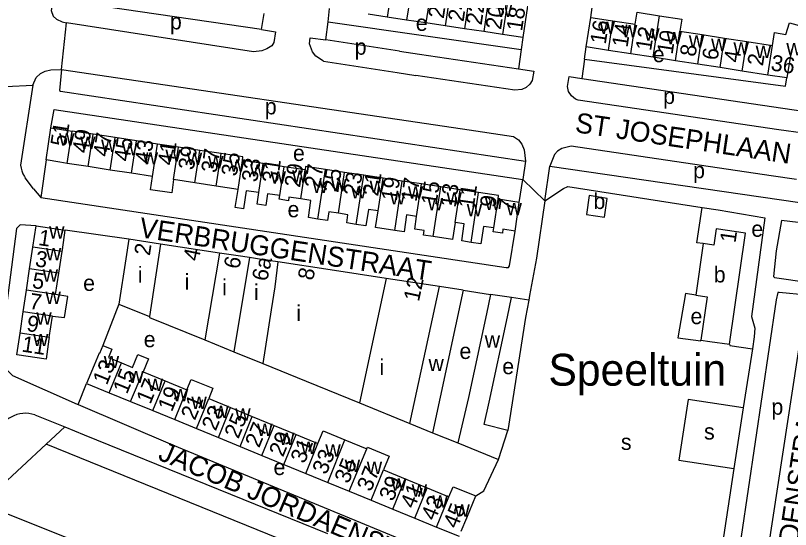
# Model space of a CAD drawing. Extents: x 163012 to 165277, y 382513 to 383987.
# Drawn here: x 163538.9 to 163733.4, y 383095.1 to 383224 of the extents above; entities that cross this region are included whole.
import ezdxf

# ---------------------------------------------------------------- set-up
doc = ezdxf.new("R2010")
doc.units = 0
for name, color, linetype in [('BLT_Basislijn', 7, 'Continuous'), ('BLT_Bebouwing', 7, 'Continuous'), ('BLT_Centroide', 7, 'Continuous'), ('BLT_Huisnummer', 7, 'Continuous'), ('BLT_Huisnummer_ tussenligend', 7, 'Continuous'), ('BLT_Onderverdeling_panden', 7, 'Continuous'), ('BLT_Straatnaam', 7, 'Continuous'), ('BLT_Terrein_beschrifting', 7, 'Continuous'), ('BLT_Vlakafsluiter', 7, 'Continuous')]:
    doc.layers.add(name, color=color, linetype=linetype)

msp = doc.modelspace()

# ---------------------------------------------------------------- linework, layer by layer
at = {"layer": 'BLT_Basislijn'}
for p, q in [((163683.27, 383223.5), (163685.34, 383238.89)), ((163617.35, 383222.35), (163617.75, 383225.74)), ((163600.65, 383220.44), (163601.31, 383224.5)), ((163616.82, 383217.83), (163617.35, 383222.35)), ((163617.35, 383222.35), (163665.8, 383215.42)), ((163666.2, 383218.45), (163665.8, 383215.42)), ((163665.8, 383215.42), (163665.17, 383210.56)), ((163681.74, 383213.01), (163682.13, 383216.08)), ((163681.74, 383213.01), (163681.06, 383208.19)), ((163616.19, 383212.49), (163634.73, 383209.65)), ((163634.73, 383209.65), (163639.41, 383208.92)), ((163543.28, 383206.52), (163540.17, 383186.47)), ((163730.5, 383195.29), (163680.12, 383202.7)), ((163547.8, 383195.77), (163548.59, 383200.4)), ((163548.59, 383200.4), (163666.28, 383182.82)), ((163546.58, 383187.75), (163545.29, 383178.34)), ((163543.44, 383180.49), (163541.32, 383183.29)), ((163665.36, 383177.07), (163666.28, 383182.82)), ((163543.44, 383180.49), (163545.29, 383178.34)), ((163567.32, 383167.86), (163551.4, 383170.14)), ((163651.24, 383155.07), (163658.14, 383154.04)), ((163667.74, 383152.57), (163663.43, 383153.24)), ((163737.55, 383153.8), (163724.03, 383065.99)), ((163564.84, 383151.6), (163560.83, 383141.22)), ((163723.85, 383140.41), (163721.57, 383125.56)), ((163554.64, 383126.39), (163556.76, 383131.68)), ((163721.57, 383125.56), (163719.24, 383110.34)), ((163543.78, 383123.82), (163551.25, 383120.79)), ((163551.25, 383120.79), (163546.61, 383116.48)), ((163551.25, 383120.79), (163556.14, 383118.81)), ((163556.14, 383118.81), (163617.19, 383094.03)), ((163643.57, 383119.33), (163649.89, 383116.83)), ((163546.61, 383116.48), (163530.49, 383101.51)), ((163712.98, 383049.04), (163546.61, 383116.48)), ((163719.24, 383110.34), (163712.93, 383069.21))]:
    msp.add_line(p, q, dxfattribs=at)
for points in [[(163548.32, 383228.18), (163547.89, 383225.23), (163548.33, 383223.8), (163549.18, 383223.01), (163550.64, 383222.36), (163551.73, 383222.16)], [(163600.65, 383220.44), (163548.32, 383228.18)], [(163600.65, 383220.44), (163604.17, 383219.84), (163603.76, 383217.22), (163603.24, 383216.36), (163602, 383215.57), (163600.74, 383215.07), (163598.63, 383214.87), (163551.73, 383222.16)], [(163616.19, 383212.49), (163614.25, 383213.75), (163613.43, 383214.84), (163612.68, 383216.9), (163612.89, 383218.37), (163616.82, 383217.83)], [(163635.28, 383215.03), (163616.82, 383217.83)], [(163635.28, 383215.03), (163640.28, 383214.25), (163665.17, 383210.56)], [(163681.74, 383213.01), (163732.21, 383206.25), (163732.54, 383208.3)], [(163543.28, 383206.52), (163544.06, 383208.45), (163545.18, 383209.44), (163546.38, 383210.05), (163547.77, 383210.35), (163550.43, 383210.46)], [(163550.43, 383210.46), (163549.94, 383205.12), (163550.2, 383204.96), (163666.92, 383187.41)], [(163550.43, 383210.46), (163651.06, 383195.58), (163663.91, 383193.63), (163665.14, 383192.82), (163665.95, 383191.74), (163666.61, 383190.28), (163666.92, 383187.41)], [(163665.17, 383210.56), (163668.97, 383210), (163668.61, 383207.65), (163668, 383206.72), (163667.11, 383205.89), (163665.99, 383205.38), (163664.21, 383205.22), (163639.41, 383208.92)], [(163680.12, 383202.7), (163679.46, 383203), (163678.46, 383203.86), (163677.67, 383204.95), (163677.49, 383206.17), (163677.86, 383208.64), (163681.06, 383208.19)], [(163681.06, 383208.19), (163743.95, 383198.89)], [(163736.58, 383194.42), (163730.5, 383195.29)], [(163728.59, 383183.8), (163678.33, 383191.17), (163676.02, 383190.64), (163674.95, 383189.93), (163674.15, 383189.07), (163673.01, 383186.2)], [(163540.17, 383186.47), (163540.29, 383185.72), (163540.5, 383184.98), (163540.78, 383184.27), (163541.14, 383183.59), (163541.32, 383183.29)], [(163666.92, 383187.41), (163666.28, 383182.82)], [(163671.78, 383177.48), (163673.01, 383186.2)], [(163673.01, 383186.2), (163740.39, 383176.4)], [(163734.93, 383182.84), (163728.59, 383183.8)], [(163671.78, 383177.48), (163676.41, 383180.57), (163677.57, 383181.06), (163711.25, 383175.83)], [(163545.29, 383178.34), (163662.05, 383160.74), (163662.63, 383160.75), (163662.91, 383161.17), (163664.28, 383169.9)], [(163671.78, 383177.48), (163669.71, 383163.15), (163667.95, 383153.73), (163667.74, 383152.57)], [(163711.51, 383166.75), (163709.91, 383166.99), (163711.25, 383175.83)], [(163711.25, 383175.83), (163715.3, 383175.2), (163726.95, 383173.25), (163723.67, 383148.52), (163723.98, 383147.31), (163724.46, 383145.55), (163724.31, 383143.4), (163723.85, 383140.41)], [(163740.23, 383171.45), (163731.14, 383172.58), (163729.82, 383164.91), (163729.17, 383158.51), (163729.43, 383158.26), (163738.07, 383157.02)], [(163544.06, 383171.23), (163540.11, 383171.45), (163539.19, 383170.51), (163535.17, 383139.55), (163535.35, 383137.13), (163535.71, 383136.14), (163538.14, 383133.7), (163554.35, 383126.52), (163554.64, 383126.39)], [(163737.55, 383153.8), (163730.58, 383154.54), (163730.22, 383154.47), (163729.85, 383152.69), (163717.55, 383069.54), (163717.76, 383068.49), (163724.03, 383065.99)], [(163709.65, 383153.82), (163707.09, 383154.26), (163705.18, 383143.11), (163710.9, 383142.39), (163710.93, 383142.57)], [(163667.74, 383152.57), (163666.93, 383148.19), (163662.45, 383119.93)], [(163718.09, 383141.54), (163718.17, 383141.25), (163723.85, 383140.41)], [(163721.57, 383125.56), (163707.76, 383127.68), (163705.39, 383112.46), (163719.24, 383110.34)], [(163554.64, 383126.39), (163578.32, 383116.28), (163648.13, 383087.42)], [(163543.78, 383123.82), (163543.03, 383124.03), (163542.27, 383124.16), (163541.49, 383124.2), (163540.72, 383124.17), (163539.96, 383124.06), (163539.21, 383123.87), (163538.48, 383123.61), (163537.78, 383123.27), (163537.12, 383122.86), (163536.51, 383122.39), (163536.02, 383121.92)], [(163654.41, 383103.48), (163656.43, 383104.8), (163660.11, 383112.66)], [(163530.49, 383101.51), (163628.79, 383062.23), (163673.84, 383043.82), (163676.87, 383042.07), (163681.18, 383038.49), (163684.68, 383034.25), (163686.91, 383030.27), (163688.82, 383025.72), (163689.82, 383019.32), (163689.3, 383011.06), (163686.97, 383004.69), (163680.5, 382995.96)]]:
    msp.add_lwpolyline(points, dxfattribs=at)
at = {"layer": 'BLT_Bebouwing'}
for p, q in [((163667.38, 383226.28), (163666.2, 383218.45)), ((163632.21, 383223.56), (163627.42, 383224.28)), ((163637.08, 383222.83), (163632.21, 383223.56)), ((163641.92, 383222.1), (163637.08, 383222.83)), ((163682.13, 383216.08), (163683.27, 383223.5)), ((163688.87, 383222.63), (163694.47, 383221.77)), ((163646.72, 383221.38), (163641.92, 383222.1)), ((163651.57, 383220.65), (163646.72, 383221.38)), ((163733.19, 383222.15), (163736.56, 383221.23)), ((163656.42, 383219.92), (163651.57, 383220.65)), ((163661.15, 383219.21), (163656.42, 383219.92)), ((163666.2, 383218.45), (163661.15, 383219.21)), ((163705.68, 383220.04), (163711.28, 383219.18)), ((163711.28, 383219.18), (163716.88, 383218.31)), ((163728.88, 383216.46), (163729.42, 383219.71)), ((163716.88, 383218.31), (163722.48, 383217.45)), ((163722.48, 383217.45), (163728.88, 383216.46)), ((163687.73, 383215.21), (163682.13, 383216.08)), ((163693.33, 383214.35), (163687.73, 383215.21)), ((163733.64, 383215.44), (163732.54, 383208.3)), ((163698.93, 383213.49), (163693.33, 383214.35)), ((163704.53, 383212.62), (163698.93, 383213.49)), ((163710.13, 383211.76), (163704.53, 383212.62)), ((163715.73, 383210.89), (163710.13, 383211.76)), ((163721.33, 383210.03), (163715.73, 383210.89)), ((163727.74, 383209.04), (163721.33, 383210.03)), ((163732.54, 383208.3), (163727.74, 383209.04)), ((163546.58, 383187.75), (163547.8, 383195.77)), ((163547.8, 383195.77), (163553.11, 383194.97)), ((163558.39, 383194.17), (163553.11, 383194.97)), ((163563.92, 383193.34), (163558.39, 383194.17)), ((163569.23, 383192.54), (163563.92, 383193.34)), ((163574.55, 383191.74), (163569.23, 383192.54)), ((163579.82, 383190.94), (163574.55, 383191.74)), ((163585.17, 383190.14), (163579.82, 383190.94)), ((163590.53, 383189.33), (163585.17, 383190.14)), ((163601.1, 383186.83), (163595.85, 383187.62)), ((163557.12, 383186.07), (163551.85, 383186.88)), ((163562.69, 383185.22), (163557.12, 383186.07)), ((163606.34, 383186.04), (163601.1, 383186.83)), ((163611.58, 383185.25), (163606.34, 383186.04)), ((163568.01, 383184.41), (163562.69, 383185.22)), ((163573.32, 383183.6), (163568.01, 383184.41)), ((163621.49, 383184.63), (163616.68, 383185.36)), ((163626.3, 383183.9), (163621.49, 383184.63)), ((163631.15, 383183.17), (163626.3, 383183.9)), ((163583.95, 383182), (163578.59, 383182.81)), ((163589.3, 383181.19), (163583.95, 383182)), ((163635.99, 383182.44), (163631.15, 383183.17)), ((163640.82, 383181.72), (163635.99, 383182.44)), ((163594.76, 383180.37), (163589.3, 383181.19)), ((163645.64, 383180.99), (163640.82, 383181.72)), ((163650.48, 383180.26), (163645.64, 383180.99)), ((163655.13, 383179.56), (163650.48, 383180.26)), ((163665.36, 383177.07), (163660.01, 383177.88)), ((163664.28, 383169.9), (163665.36, 383177.07)), ((163543.26, 383165.85), (163544.06, 383171.23)), ((163544.06, 383171.23), (163551.4, 383170.14)), ((163575.33, 383166.64), (163567.32, 383167.86)), ((163590.12, 383164.38), (163575.33, 383166.64)), ((163711.51, 383166.75), (163709.65, 383153.82)), ((163714.17, 383166.37), (163711.51, 383166.75)), ((163542.45, 383160.46), (163543.26, 383165.85)), ((163549.79, 383159.37), (163550.59, 383164.76)), ((163594.82, 383163.67), (163590.12, 383164.38)), ((163597.62, 383163.24), (163594.82, 383163.67)), ((163601.62, 383162.63), (163597.62, 383163.24)), ((163604.71, 383162.16), (163601.62, 383162.63)), ((163541.65, 383155.08), (163542.45, 383160.46)), ((163617.84, 383160.16), (163604.71, 383162.16)), ((163548.98, 383153.98), (163549.79, 383159.37)), ((163631.97, 383158.01), (163617.84, 383160.16)), ((163645.33, 383155.97), (163631.97, 383158.01)), ((163540.84, 383149.69), (163541.65, 383155.08)), ((163651.24, 383155.07), (163643.57, 383119.33)), ((163651.24, 383155.07), (163645.33, 383155.97)), ((163663.43, 383153.24), (163658.14, 383154.04)), ((163564.84, 383151.6), (163572.56, 383148.48)), ((163540.04, 383144.3), (163540.84, 383149.69)), ((163547.37, 383143.2), (163548.18, 383148.59)), ((163586.43, 383142.61), (163593.66, 383139.66)), ((163710.93, 383142.57), (163713.14, 383142.25)), ((163713.14, 383142.25), (163718.09, 383141.54)), ((163593.66, 383139.66), (163600.97, 383136.68)), ((163600.97, 383136.68), (163611.86, 383132.25)), ((163570.97, 383134.61), (163576.45, 383132.37)), ((163556.76, 383131.68), (163562.42, 383129.36)), ((163576.45, 383132.37), (163581.93, 383130.12)), ((163611.86, 383132.25), (163625.26, 383126.83)), ((163562.42, 383129.36), (163567.76, 383127.18)), ((163587.41, 383127.89), (163592.89, 383125.65)), ((163567.76, 383127.18), (163573.38, 383124.87)), ((163625.26, 383126.83), (163637.88, 383121.64)), ((163573.38, 383124.87), (163578.86, 383122.62)), ((163598.33, 383123.4), (163603.83, 383121.15)), ((163578.86, 383122.62), (163584.33, 383120.38)), ((163637.88, 383121.64), (163643.57, 383119.33)), ((163584.33, 383120.38), (163589.81, 383118.13)), ((163603.83, 383121.15), (163609.33, 383118.9)), ((163589.81, 383118.13), (163595.26, 383115.9)), ((163609.33, 383118.9), (163614.81, 383116.65)), ((163595.26, 383115.9), (163600.76, 383113.65)), ((163621.57, 383117.56), (163627.11, 383115.31)), ((163600.76, 383113.65), (163606.26, 383111.39)), ((163606.26, 383111.39), (163611.76, 383109.14)), ((163631.26, 383109.99), (163636.73, 383107.74)), ((163611.76, 383109.14), (163617.26, 383106.88)), ((163617.26, 383106.88), (163622.68, 383104.66)), ((163636.73, 383107.74), (163642.21, 383105.49)), ((163622.68, 383104.66), (163628.15, 383102.42)), ((163642.21, 383105.49), (163647.69, 383103.25)), ((163628.15, 383102.42), (163633.63, 383100.17)), ((163633.63, 383100.17), (163639.11, 383097.93)), ((163639.11, 383097.93), (163644.59, 383095.68)), ((163644.59, 383095.68), (163650.26, 383093.36))]:
    msp.add_line(p, q, dxfattribs=at)
for points in [[(163694.47, 383221.77), (163694.94, 383224.78), (163700.54, 383223.91)], [(163683.27, 383223.5), (163688.21, 383222.73), (163688.87, 383222.63)], [(163700.54, 383223.91), (163706.14, 383223.05), (163705.68, 383220.04)], [(163729.42, 383219.71), (163732.23, 383219.23), (163733.19, 383222.15)], [(163551.85, 383186.88), (163550.05, 383187.16), (163546.58, 383187.75)], [(163595.85, 383187.62), (163595.98, 383188.51), (163590.53, 383189.33)], [(163616.68, 383185.36), (163611.71, 383186.1), (163611.58, 383185.25)], [(163578.59, 383182.81), (163578.14, 383179.47), (163572.82, 383180.27), (163573.32, 383183.6)], [(163600, 383179.54), (163596.78, 383180.02), (163596.1, 383175.49), (163594.07, 383175.8), (163594.76, 383180.37)], [(163605.25, 383178.79), (163602.15, 383179.26), (163601.71, 383176.32), (163599.56, 383176.64), (163600, 383179.54)], [(163610.49, 383178), (163607.52, 383178.45), (163607.39, 383177.53), (163605.11, 383177.87), (163605.25, 383178.79)], [(163614.8, 383172.91), (163612.4, 383173.27), (163613.05, 383177.61), (163610.49, 383178)], [(163660.01, 383177.88), (163660.15, 383178.8), (163655.13, 383179.56)], [(163619.94, 383174.38), (163617.54, 383174.74), (163617.21, 383172.55), (163614.8, 383172.91)], [(163624.44, 383171.57), (163622.03, 383171.94), (163622.34, 383174.01), (163619.94, 383174.38)], [(163629.92, 383174.98), (163627.48, 383175.35), (163626.86, 383171.21), (163624.44, 383171.57)], [(163634.13, 383170.08), (163629.29, 383170.81), (163629.92, 383174.98)], [(163639.59, 383173.57), (163637.08, 383173.95), (163636.44, 383169.73), (163634.13, 383170.08)], [(163643.76, 383168.55), (163641.33, 383168.92), (163641.5, 383170.01), (163639.11, 383170.37), (163639.59, 383173.57)], [(163550.59, 383164.76), (163550.66, 383165.19), (163551.4, 383170.14)], [(163649.25, 383172.03), (163648.61, 383167.82), (163643.76, 383168.55)], [(163653.31, 383167.08), (163650.9, 383167.43), (163651.54, 383171.69), (163649.25, 383172.03)], [(163658.93, 383170.71), (163656.38, 383171.07), (163655.73, 383166.73), (163653.31, 383167.08)], [(163664.28, 383169.9), (163661.26, 383170.36), (163661.11, 383169.36), (163658.78, 383169.71), (163658.93, 383170.71)], [(163718.09, 383141.54), (163722.09, 383169.38), (163714.75, 383170.44), (163714.17, 383166.37)], [(163567.32, 383167.86), (163566.56, 383162.92), (163564.84, 383151.6)], [(163548.18, 383148.59), (163551.2, 383148.2), (163552, 383153.53), (163548.98, 383153.98)], [(163658.14, 383154.04), (163657.08, 383149.15), (163652.56, 383128.13)], [(163662.45, 383119.93), (163656.56, 383121.36), (163657.78, 383127), (163662.38, 383148.36), (163663.43, 383153.24)], [(163709.65, 383153.82), (163712.48, 383153.41), (163710.93, 383142.57)], [(163572.56, 383148.48), (163572.53, 383148.27), (163586.43, 383142.61)], [(163547.37, 383143.2), (163547.3, 383142.76), (163546.57, 383137.82), (163539.23, 383138.91), (163540.04, 383144.3)], [(163560.83, 383141.22), (163560, 383139.2), (163559.86, 383139.25), (163558.65, 383136.31), (163556.76, 383131.68)], [(163560.83, 383141.22), (163563.07, 383140.3), (163562.2, 383138.21), (163565.49, 383136.86)], [(163565.49, 383136.86), (163568.27, 383135.72), (163569.59, 383138.93), (163572.29, 383137.83), (163570.97, 383134.61)], [(163581.93, 383130.12), (163582.99, 383132.71), (163588.47, 383130.47), (163587.41, 383127.89)], [(163652.56, 383128.13), (163649.89, 383116.83)], [(163592.89, 383125.65), (163598.33, 383123.4)], [(163614.81, 383116.65), (163616.1, 383119.78), (163621.57, 383117.56)], [(163660.11, 383112.66), (163662.45, 383119.93)], [(163627.11, 383115.31), (163627.27, 383115.7), (163632.69, 383113.48), (163631.26, 383109.99)], [(163649.89, 383116.83), (163660.11, 383112.66)], [(163647.69, 383103.25), (163648.74, 383105.8), (163654.41, 383103.48)], [(163650.77, 383094.61), (163652.15, 383097.98), (163654.41, 383103.48)]]:
    msp.add_lwpolyline(points, dxfattribs=at)
msp.add_lwpolyline([(163682.92, 383178.79), (163682.19, 383174.1), (163686.7, 383173.39), (163687.43, 383178.08)], close=True, dxfattribs=at)
at = {"layer": 'BLT_Onderverdeling_panden'}
for p, q in [((163634.08, 383235.99), (163632.21, 383223.56)), ((163643.8, 383234.55), (163641.92, 383222.1)), ((163653.43, 383233.05), (163651.57, 383220.65)), ((163638.33, 383231.09), (163637.08, 383222.83)), ((163663.01, 383231.59), (163661.15, 383219.21)), ((163647.96, 383229.63), (163646.72, 383221.38)), ((163657.64, 383228.16), (163656.42, 383219.92)), ((163687.73, 383215.21), (163688.87, 383222.63)), ((163698.93, 383213.49), (163700.54, 383223.91)), ((163693.33, 383214.35), (163694.47, 383221.77)), ((163704.53, 383212.62), (163705.68, 383220.04)), ((163710.13, 383211.76), (163711.28, 383219.18)), ((163715.73, 383210.89), (163716.88, 383218.31)), ((163721.33, 383210.03), (163722.48, 383217.45)), ((163727.74, 383209.04), (163728.88, 383216.46)), ((163551.85, 383186.88), (163553.11, 383194.97)), ((163557.12, 383186.07), (163558.39, 383194.17)), ((163562.69, 383185.22), (163563.92, 383193.34)), ((163568.01, 383184.41), (163569.23, 383192.54)), ((163573.32, 383183.6), (163574.55, 383191.74)), ((163578.59, 383182.81), (163579.82, 383190.94)), ((163583.95, 383182), (163585.17, 383190.14)), ((163589.3, 383181.19), (163590.53, 383189.33)), ((163594.76, 383180.37), (163595.85, 383187.62)), ((163600, 383179.54), (163601.1, 383186.83)), ((163605.25, 383178.79), (163606.34, 383186.04)), ((163610.49, 383178), (163611.58, 383185.25)), ((163614.8, 383172.91), (163616.68, 383185.36)), ((163619.94, 383174.38), (163621.49, 383184.63)), ((163624.44, 383171.57), (163626.3, 383183.9)), ((163629.92, 383174.98), (163631.15, 383183.17)), ((163634.13, 383170.08), (163635.99, 383182.44)), ((163639.59, 383173.57), (163640.82, 383181.72)), ((163643.76, 383168.55), (163645.64, 383180.99)), ((163649.25, 383172.03), (163650.48, 383180.26)), ((163653.31, 383167.08), (163655.13, 383179.56)), ((163658.93, 383170.71), (163660.01, 383177.88)), ((163575.33, 383166.64), (163572.56, 383148.48)), ((163550.59, 383164.76), (163543.26, 383165.85)), ((163590.12, 383164.38), (163586.43, 383142.61)), ((163597.62, 383163.24), (163593.66, 383139.66)), ((163549.79, 383159.37), (163542.45, 383160.46)), ((163631.97, 383158.01), (163625.26, 383126.83)), ((163548.98, 383153.98), (163541.65, 383155.08)), ((163637.88, 383121.64), (163645.33, 383155.97)), ((163548.18, 383148.59), (163540.84, 383149.69)), ((163547.37, 383143.2), (163540.04, 383144.3)), ((163562.42, 383129.36), (163565.49, 383136.86)), ((163567.76, 383127.18), (163570.97, 383134.61)), ((163573.38, 383124.87), (163576.45, 383132.37)), ((163578.86, 383122.62), (163581.93, 383130.12)), ((163584.33, 383120.38), (163587.41, 383127.89)), ((163589.81, 383118.13), (163592.89, 383125.65)), ((163595.26, 383115.9), (163598.33, 383123.4)), ((163600.76, 383113.65), (163603.83, 383121.15)), ((163606.26, 383111.39), (163609.33, 383118.9)), ((163611.76, 383109.14), (163614.81, 383116.65)), ((163617.26, 383106.88), (163621.57, 383117.56)), ((163622.68, 383104.66), (163627.11, 383115.31)), ((163628.15, 383102.42), (163631.26, 383109.99)), ((163633.63, 383100.17), (163636.73, 383107.74)), ((163639.11, 383097.93), (163642.21, 383105.49)), ((163644.59, 383095.68), (163647.69, 383103.25))]:
    msp.add_line(p, q, dxfattribs=at)
msp.add_lwpolyline([(163604.71, 383162.16), (163603.96, 383155.95), (163603.08, 383150.13), (163600.97, 383136.68)], dxfattribs=at)
at = {"layer": 'BLT_Vlakafsluiter'}
for p, q in [((163550.43, 383210.46), (163551.73, 383222.16)), ((163536.45, 383206.14), (163543.28, 383206.52)), ((163671.78, 383177.48), (163666.28, 383182.82))]:
    msp.add_line(p, q, dxfattribs=at)

# ---------------------------------------------------------------- texts
at = {"layer": 'BLT_Centroide'}
for s, p in [('w', (163659.72, 383223.62)), ('p', (163577.66, 383220.49)), ('e', (163639.37, 383220.12)), ('w', (163685.5, 383219.36)), ('w', (163691.09, 383218.48)), ('w', (163696.7, 383217.64)), ('w', (163702.3, 383216.77)), ('w', (163707.91, 383215.89)), ('p', (163624.04, 383214.13)), ('w', (163713.5, 383215.05)), ('w', (163719.11, 383214.17)), ('w', (163732.38, 383214)), ('e', (163698.85, 383212.26)), ('w', (163724.7, 383213.3)), ('p', (163701.46, 383201.78)), ('p', (163601.48, 383199.17)), ('w', (163549.84, 383191.33)), ('w', (163555.12, 383190.52)), ('w', (163560.39, 383189.72)), ('w', (163565.66, 383188.92)), ('w', (163570.84, 383186.62)), ('w', (163576.53, 383187.28)), ('e', (163608.54, 383187.49)), ('w', (163581.89, 383186.47)), ('w', (163587.23, 383185.66)), ('w', (163592.64, 383184.84)), ('w', (163597.75, 383183.61)), ('p', (163708.98, 383183.15)), ('w', (163602.92, 383181.78)), ('w', (163608.33, 383182.03)), ('w', (163613.45, 383179.48)), ('w', (163618.14, 383179.89)), ('w', (163627.78, 383179.5)), ('w', (163623.12, 383178.08)), ('w', (163637.39, 383178.06)), ('w', (163632.89, 383176.58)), ('w', (163642.34, 383175.12)), ('w', (163647.09, 383176.56)), ('w', (163656.73, 383175.17)), ('b', (163683.97, 383175.44)), ('e', (163607.18, 383173.37)), ('w', (163652.16, 383173.62)), ('w', (163662.14, 383173.89)), ('w', (163547.33, 383168)), ('e', (163723.6, 383168.47)), ('w', (163546.52, 383162.59)), ('i', (163569.59, 383156.97)), ('b', (163714.16, 383157.02)), ('w', (163545.72, 383157.22)), ('i', (163581.33, 383155.2)), ('e', (163555.88, 383154.9)), ('i', (163590.78, 383153.8)), ('i', (163598.76, 383152.58)), ('w', (163546.42, 383151.62)), ('i', (163609.36, 383147.34)), ('w', (163544.11, 383146.44)), ('e', (163708.33, 383146.57)), ('w', (163543.3, 383141.06)), ('e', (163571.08, 383140.77)), ('w', (163656.67, 383140.69)), ('e', (163650.34, 383137.83)), ('w', (163561.05, 383135.53)), ('i', (163630.25, 383133.79)), ('w', (163642.56, 383134.79)), ('e', (163661.08, 383134.01)), ('w', (163567.22, 383131.78)), ('w', (163572.05, 383129.8)), ('w', (163578.39, 383127.2)), ('w', (163583.05, 383125.3)), ('w', (163588.55, 383123.05)), ('w', (163594.05, 383122.34)), ('p', (163728.63, 383123.85)), ('w', (163599.55, 383118.53)), ('s', (163711.72, 383117.63)), ('w', (163605.05, 383116.27)), ('s', (163690.86, 383115.02)), ('w', (163610.53, 383114.02)), ('w', (163616.66, 383113.34)), ('e', (163603.66, 383108.72)), ('w', (163621.53, 383109.52)), ('w', (163627.06, 383109.02)), ('w', (163633.16, 383104.8)), ('w', (163638.33, 383103.33)), ('w', (163643.56, 383100.52)), ('w', (163649.06, 383098.27))]:
    msp.add_text(s, height=4, dxfattribs=at).set_placement(p)
at = {"layer": 'BLT_Huisnummer'}
for s, rotation, p in [('26', 81.4421, (163646.38, 383223.05)), ('22', 81.4371, (163655.88, 383221.42)), ('18', 81.4413, (163666.03, 383219.89)), ('16', 81.2329, (163687.03, 383216.61)), ('10', 81.2254, (163703.81, 383214.08)), ('6', 81.2254, (163715.12, 383212.6)), ('2', 81.2254, (163726.49, 383211.15)), ('36', 351.2297, (163728.32, 383210.23)), ('51', 81.1386, (163551.57, 383190.97)), ('47', 81.1321, (163562.27, 383188.38)), ('43', 81.4376, (163572.71, 383186.68)), ('39', 81.4307, (163583.63, 383185.07)), ('35', 81.4399, (163594.43, 383183.5)), ('31', 81.438, (163604.66, 383181.78)), ('27', 81.4229, (163615.34, 383180.5)), ('23', 81.4211, (163625.13, 383178.55)), ('19', 81.428, (163634.59, 383177.29)), ('15', 81.4355, (163644.59, 383176.27)), ('11', 81.6977, (163653.92, 383175.44)), ('7', 81.427, (163664.05, 383174.6)), ('1', 351.5051, (163544.46, 383166.42)), ('1', 81.8193, (163719.62, 383166.83)), ('2', 81.3369, (163572.61, 383163.59)), ('4', 77.8998, (163584.82, 383162.17)), ('6', 77.8991, (163595, 383160.2)), ('6a', 77.8991, (163602.06, 383157.15)), ('8', 77.8991, (163613.56, 383157.35)), ('5', 351.4952, (163542.91, 383155.67)), ('12', 77.8991, (163640.15, 383152.06)), ('11', 351.5017, (163540.3, 383139.71)), ('13', 67.7099, (163561.82, 383131.09)), ('17', 67.7109, (163572.75, 383126.3)), ('21', 67.707, (163583.93, 383122.28)), ('25', 67.7075, (163594.84, 383117.64)), ('29', 67.7114, (163606.05, 383113.07)), ('33', 67.7082, (163616.91, 383108.63)), ('37', 67.7106, (163628.11, 383104.36)), ('41', 67.7087, (163638.99, 383100.08)), ('45', 67.7091, (163649.74, 383095.07))]:
    msp.add_text(s, height=4, rotation=rotation, dxfattribs=at).set_placement(p)
at = {"layer": 'BLT_Huisnummer_ tussenligend'}
for s, rotation, p in [('24', 81.4371, (163651.35, 383222.27)), ('20', 81.4413, (163660.77, 383220.29)), ('14', 81.2254, (163692.51, 383215.82)), ('12', 81.2254, (163698.42, 383214.97)), ('8', 81.2254, (163709.55, 383213.48)), ('4', 81.2254, (163720.58, 383212)), ('49', 81.1321, (163557.05, 383189.25)), ('45', 81.4376, (163567.49, 383187.2)), ('41', 81.4307, (163578.48, 383186.22)), ('37', 81.4399, (163589.39, 383184.36)), ('33', 81.438, (163599.56, 383182.03)), ('29', 81.4229, (163610.3, 383180.68)), ('25', 81.4211, (163619.91, 383179.42)), ('21', 81.428, (163629.92, 383178.5)), ('17', 81.4355, (163639.54, 383177.12)), ('13', 81.6977, (163649.34, 383175.69)), ('9', 81.427, (163659.35, 383175.65)), ('3', 351.5051, (163543.66, 383161.09)), ('7', 351.4952, (163542.2, 383150.45)), ('9', 351.4952, (163541.52, 383144.88)), ('15', 67.7099, (163566.87, 383128.83)), ('19', 67.7109, (163578.14, 383124.39)), ('23', 67.707, (163589.15, 383119.6)), ('27', 67.7075, (163600.05, 383115.36)), ('31', 67.7114, (163611.44, 383111.4)), ('35', 67.7082, (163622.48, 383106.37)), ('39', 67.7106, (163633.68, 383101.94)), ('43', 67.7087, (163644.21, 383097.05))]:
    msp.add_text(s, height=4, rotation=rotation, dxfattribs=at).set_placement(p)
at = {"layer": 'BLT_Straatnaam'}
for s, height, rotation, p in [('ST JOSEPHLAAN', 5, 351.6214, (163679.15, 383194.72)), ('VERBRUGGENSTRAAT', 4.9999, 351.4375, (163569.71, 383168.41)), ('ROGIER VAN DER WEYDENSTRAAT', 5, 81.5474, (163724.32, 383017.21)), ('JACOB JORDAENSWEG', 5, 336.9433, (163574.4, 383112.7))]:
    msp.add_text(s, height=height, rotation=rotation, dxfattribs=at).set_placement(p)
at = {"layer": 'BLT_Terrein_beschrifting'}
msp.add_text('Speeltuin', height=8, dxfattribs=at).set_placement((163672.67, 383131.13))

doc.saveas('drawing.dxf')
